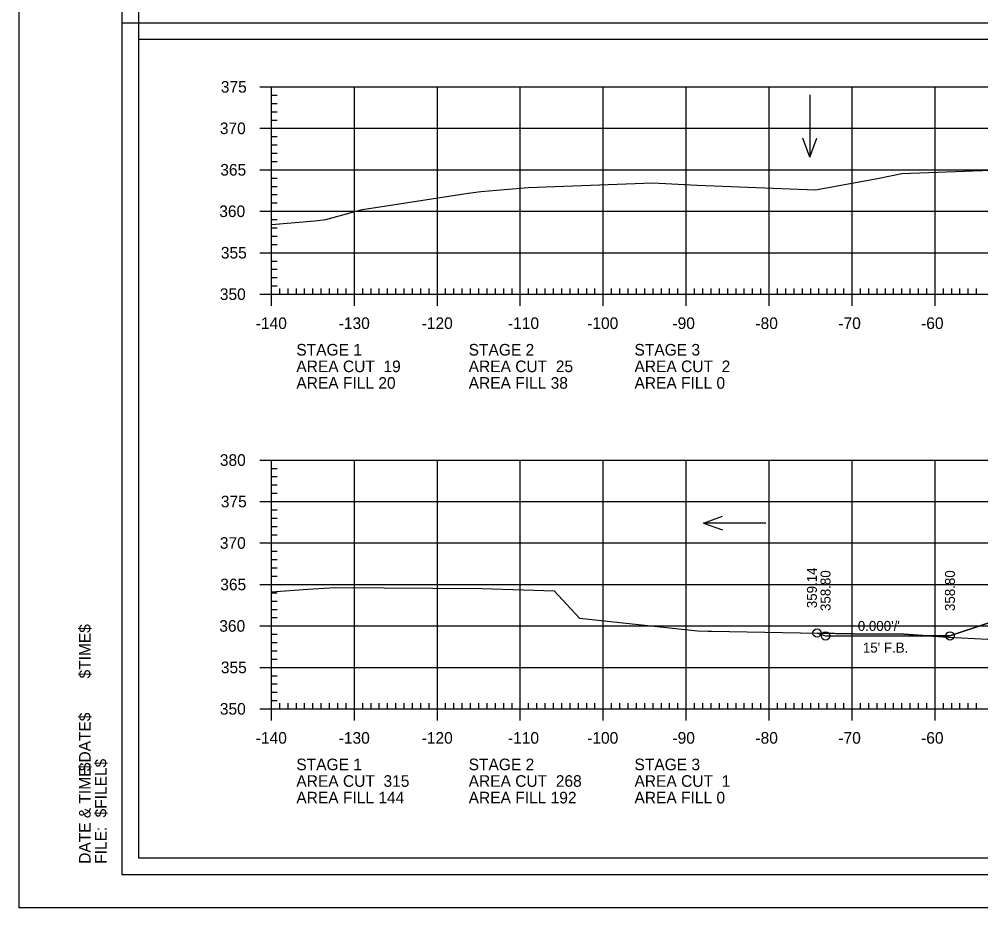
# Model space of a CAD drawing. Extents: x 1368910 to 1369601, y 380116 to 380950.
# Drawn here: x 1368909.8 to 1369025.7, y 380523.8 to 380630.9 of the extents above; entities that cross this region are included whole.
import ezdxf

# ---------------------------------------------------------------- set-up
doc = ezdxf.new("R2010")
doc.units = 0
for name, color, linetype in [('_STAGE 2 CUT', 7, 'Continuous'), ('_STAGE 2 FILL', 7, 'Continuous'), ('R_Axis', 7, 'Continuous'), ('R_Axis Annot', 7, 'Continuous'), ('R_Border', 7, 'Continuous'), ('R_Border Notes', 7, 'Continuous'), ('R_Border Plan-Plan', 7, 'Continuous'), ('R_Exist Surface', 7, 'Continuous'), ('R_Fin Surface', 7, 'Continuous'), ('R_Grid', 7, 'Continuous'), ('R_No Plot', 7, 'Continuous'), ('R_Water Annot', 7, 'Continuous'), ('R_Xsect Elev', 7, 'Continuous'), ('R_Xsect Slope', 7, 'Continuous')]:
    doc.layers.add(name, color=color, linetype=linetype)

msp = doc.modelspace()

# ---------------------------------------------------------------- linework, layer by layer
at = {"layer": '_STAGE 2 CUT'}
for points in [[(1369019.31, 380556.56), (1369016.48, 380556.75), (1369010.41, 380556.82), (1369010.24, 380556.82), (1369006.01, 380556.9)], [(1369006.01, 380556.9), (1369007.03, 380556.56), (1369010.24, 380556.56), (1369019.31, 380556.56)]]:
    msp.add_lwpolyline(points, dxfattribs=at)
at = {"layer": '_STAGE 2 FILL'}
for points in [[(1369019.31, 380556.56), (1369021.84, 380556.39), (1369031.24, 380555.91), (1369035.71, 380555.81), (1369040.24, 380555.68), (1369046.32, 380555.51), (1369049.52, 380557.76), (1369050.24, 380558.27), (1369056.62, 380562.76), (1369060.24, 380565.31), (1369061.88, 380566.47)], [(1369055.52, 380566.34), (1369050.24, 380565.46), (1369047.24, 380564.96), (1369040.63, 380562.76), (1369040.24, 380562.63), (1369025.63, 380557.76), (1369022.03, 380556.56), (1369019.31, 380556.56)]]:
    msp.add_lwpolyline(points, dxfattribs=at)
at = {"layer": 'R_Axis'}
for p, q in [((1368938.84, 380622.76), (1368941.64, 380622.76)), ((1368940.24, 380597.76), (1368940.24, 380622.76)), ((1368940.24, 380621.76), (1368940.94, 380621.76)), ((1368940.24, 380620.76), (1368940.94, 380620.76)), ((1368940.24, 380619.76), (1368940.94, 380619.76)), ((1368940.24, 380618.76), (1368940.94, 380618.76)), ((1368938.84, 380617.76), (1368941.64, 380617.76)), ((1368940.24, 380616.76), (1368940.94, 380616.76)), ((1368940.24, 380615.76), (1368940.94, 380615.76)), ((1368940.24, 380614.76), (1368940.94, 380614.76)), ((1368940.24, 380613.76), (1368940.94, 380613.76)), ((1368938.84, 380612.76), (1368941.64, 380612.76)), ((1368940.24, 380611.76), (1368940.94, 380611.76)), ((1368940.24, 380610.76), (1368940.94, 380610.76)), ((1368940.24, 380609.76), (1368940.94, 380609.76)), ((1368938.84, 380607.76), (1368941.64, 380607.76)), ((1368940.24, 380608.76), (1368940.94, 380608.76)), ((1368940.24, 380606.76), (1368940.94, 380606.76)), ((1368940.24, 380605.76), (1368940.94, 380605.76)), ((1368940.24, 380604.76), (1368940.94, 380604.76)), ((1368940.24, 380603.76), (1368940.94, 380603.76)), ((1368938.84, 380602.76), (1368941.64, 380602.76)), ((1368940.24, 380601.76), (1368940.94, 380601.76)), ((1368940.24, 380600.76), (1368940.94, 380600.76)), ((1368940.24, 380599.76), (1368940.94, 380599.76)), ((1368940.24, 380596.36), (1368940.24, 380599.16)), ((1368940.24, 380598.76), (1368940.94, 380598.76)), ((1368941.24, 380597.76), (1368941.24, 380598.46)), ((1368942.24, 380597.76), (1368942.24, 380598.46)), ((1368943.24, 380597.76), (1368943.24, 380598.46)), ((1368944.24, 380597.76), (1368944.24, 380598.46)), ((1368945.24, 380597.76), (1368945.24, 380598.46)), ((1368946.24, 380597.76), (1368946.24, 380598.46)), ((1368947.24, 380597.76), (1368947.24, 380598.46)), ((1368948.24, 380597.76), (1368948.24, 380598.46)), ((1368949.24, 380597.76), (1368949.24, 380598.46)), ((1368950.24, 380596.36), (1368950.24, 380599.16)), ((1368951.24, 380597.76), (1368951.24, 380598.46)), ((1368952.24, 380597.76), (1368952.24, 380598.46)), ((1368953.24, 380597.76), (1368953.24, 380598.46)), ((1368954.24, 380597.76), (1368954.24, 380598.46)), ((1368955.24, 380597.76), (1368955.24, 380598.46)), ((1368956.24, 380597.76), (1368956.24, 380598.46)), ((1368957.24, 380597.76), (1368957.24, 380598.46)), ((1368958.24, 380597.76), (1368958.24, 380598.46)), ((1368959.24, 380597.76), (1368959.24, 380598.46)), ((1368960.24, 380596.36), (1368960.24, 380599.16)), ((1368961.24, 380597.76), (1368961.24, 380598.46)), ((1368962.24, 380597.76), (1368962.24, 380598.46)), ((1368963.24, 380597.76), (1368963.24, 380598.46)), ((1368964.24, 380597.76), (1368964.24, 380598.46)), ((1368965.24, 380597.76), (1368965.24, 380598.46)), ((1368966.24, 380597.76), (1368966.24, 380598.46)), ((1368967.24, 380597.76), (1368967.24, 380598.46)), ((1368968.24, 380597.76), (1368968.24, 380598.46)), ((1368969.24, 380597.76), (1368969.24, 380598.46)), ((1368970.24, 380596.36), (1368970.24, 380599.16)), ((1368971.24, 380597.76), (1368971.24, 380598.46)), ((1368972.24, 380597.76), (1368972.24, 380598.46)), ((1368973.24, 380597.76), (1368973.24, 380598.46)), ((1368974.24, 380597.76), (1368974.24, 380598.46)), ((1368975.24, 380597.76), (1368975.24, 380598.46)), ((1368976.24, 380597.76), (1368976.24, 380598.46)), ((1368977.24, 380597.76), (1368977.24, 380598.46)), ((1368978.24, 380597.76), (1368978.24, 380598.46)), ((1368979.24, 380597.76), (1368979.24, 380598.46)), ((1368980.24, 380596.36), (1368980.24, 380599.16)), ((1368981.24, 380597.76), (1368981.24, 380598.46)), ((1368982.24, 380597.76), (1368982.24, 380598.46)), ((1368983.24, 380597.76), (1368983.24, 380598.46)), ((1368984.24, 380597.76), (1368984.24, 380598.46)), ((1368985.24, 380597.76), (1368985.24, 380598.46)), ((1368986.24, 380597.76), (1368986.24, 380598.46)), ((1368987.24, 380597.76), (1368987.24, 380598.46)), ((1368988.24, 380597.76), (1368988.24, 380598.46)), ((1368989.24, 380597.76), (1368989.24, 380598.46)), ((1368990.24, 380596.36), (1368990.24, 380599.16)), ((1368991.24, 380597.76), (1368991.24, 380598.46)), ((1368992.24, 380597.76), (1368992.24, 380598.46)), ((1368993.24, 380597.76), (1368993.24, 380598.46)), ((1368994.24, 380597.76), (1368994.24, 380598.46)), ((1368995.24, 380597.76), (1368995.24, 380598.46)), ((1368996.24, 380597.76), (1368996.24, 380598.46)), ((1368997.24, 380597.76), (1368997.24, 380598.46)), ((1368998.24, 380597.76), (1368998.24, 380598.46)), ((1368999.24, 380597.76), (1368999.24, 380598.46)), ((1369000.24, 380596.36), (1369000.24, 380599.16)), ((1369001.24, 380597.76), (1369001.24, 380598.46)), ((1369002.24, 380597.76), (1369002.24, 380598.46)), ((1369003.24, 380597.76), (1369003.24, 380598.46)), ((1369004.24, 380597.76), (1369004.24, 380598.46)), ((1369005.24, 380597.76), (1369005.24, 380598.46)), ((1369006.24, 380597.76), (1369006.24, 380598.46)), ((1369007.24, 380597.76), (1369007.24, 380598.46)), ((1369008.24, 380597.76), (1369008.24, 380598.46)), ((1369009.24, 380597.76), (1369009.24, 380598.46)), ((1369010.24, 380596.36), (1369010.24, 380599.16)), ((1369011.24, 380597.76), (1369011.24, 380598.46)), ((1369012.24, 380597.76), (1369012.24, 380598.46)), ((1369013.24, 380597.76), (1369013.24, 380598.46)), ((1369014.24, 380597.76), (1369014.24, 380598.46)), ((1369015.24, 380597.76), (1369015.24, 380598.46)), ((1369016.24, 380597.76), (1369016.24, 380598.46)), ((1369017.24, 380597.76), (1369017.24, 380598.46)), ((1369018.24, 380597.76), (1369018.24, 380598.46)), ((1369019.24, 380597.76), (1369019.24, 380598.46)), ((1369020.24, 380596.36), (1369020.24, 380599.16)), ((1369021.24, 380597.76), (1369021.24, 380598.46)), ((1369022.24, 380597.76), (1369022.24, 380598.46)), ((1369023.24, 380597.76), (1369023.24, 380598.46)), ((1369024.24, 380597.76), (1369024.24, 380598.46)), ((1369025.24, 380597.76), (1369025.24, 380598.46)), ((1368938.84, 380597.76), (1368941.64, 380597.76)), ((1368940.24, 380597.76), (1369220.24, 380597.76)), ((1368938.84, 380577.76), (1368941.64, 380577.76)), ((1368940.24, 380547.76), (1368940.24, 380577.76)), ((1368940.24, 380576.76), (1368940.94, 380576.76)), ((1368940.24, 380575.76), (1368940.94, 380575.76)), ((1368940.24, 380574.76), (1368940.94, 380574.76)), ((1368940.24, 380573.76), (1368940.94, 380573.76)), ((1368938.84, 380572.76), (1368941.64, 380572.76)), ((1368940.24, 380571.76), (1368940.94, 380571.76)), ((1368940.24, 380570.76), (1368940.94, 380570.76)), ((1368940.24, 380569.76), (1368940.94, 380569.76)), ((1368940.24, 380568.76), (1368940.94, 380568.76)), ((1368938.84, 380567.76), (1368941.64, 380567.76)), ((1368940.24, 380566.76), (1368940.94, 380566.76)), ((1368940.24, 380565.76), (1368940.94, 380565.76)), ((1368940.24, 380564.76), (1368940.94, 380564.76)), ((1368940.24, 380563.76), (1368940.94, 380563.76)), ((1368938.84, 380562.76), (1368941.64, 380562.76)), ((1368940.24, 380561.76), (1368940.94, 380561.76)), ((1368940.24, 380560.76), (1368940.94, 380560.76)), ((1368940.24, 380559.76), (1368940.94, 380559.76)), ((1368940.24, 380558.76), (1368940.94, 380558.76)), ((1368938.84, 380557.76), (1368941.64, 380557.76)), ((1368940.24, 380556.76), (1368940.94, 380556.76)), ((1368940.24, 380555.76), (1368940.94, 380555.76)), ((1368940.24, 380554.76), (1368940.94, 380554.76)), ((1368940.24, 380553.76), (1368940.94, 380553.76)), ((1368938.84, 380552.76), (1368941.64, 380552.76)), ((1368940.24, 380551.76), (1368940.94, 380551.76)), ((1368940.24, 380550.76), (1368940.94, 380550.76)), ((1368940.24, 380549.76), (1368940.94, 380549.76)), ((1368940.24, 380546.36), (1368940.24, 380549.16)), ((1368940.24, 380548.76), (1368940.94, 380548.76)), ((1368950.24, 380546.36), (1368950.24, 380549.16)), ((1368960.24, 380546.36), (1368960.24, 380549.16)), ((1368970.24, 380546.36), (1368970.24, 380549.16)), ((1368980.24, 380546.36), (1368980.24, 380549.16)), ((1368990.24, 380546.36), (1368990.24, 380549.16)), ((1369000.24, 380546.36), (1369000.24, 380549.16)), ((1369010.24, 380546.36), (1369010.24, 380549.16)), ((1369020.24, 380546.36), (1369020.24, 380549.16)), ((1368938.84, 380547.76), (1368941.64, 380547.76)), ((1368940.24, 380547.76), (1369220.24, 380547.76)), ((1368941.24, 380547.76), (1368941.24, 380548.46)), ((1368942.24, 380547.76), (1368942.24, 380548.46)), ((1368943.24, 380547.76), (1368943.24, 380548.46)), ((1368944.24, 380547.76), (1368944.24, 380548.46)), ((1368945.24, 380547.76), (1368945.24, 380548.46)), ((1368946.24, 380547.76), (1368946.24, 380548.46)), ((1368947.24, 380547.76), (1368947.24, 380548.46)), ((1368948.24, 380547.76), (1368948.24, 380548.46)), ((1368949.24, 380547.76), (1368949.24, 380548.46)), ((1368951.24, 380547.76), (1368951.24, 380548.46)), ((1368952.24, 380547.76), (1368952.24, 380548.46)), ((1368953.24, 380547.76), (1368953.24, 380548.46)), ((1368954.24, 380547.76), (1368954.24, 380548.46)), ((1368955.24, 380547.76), (1368955.24, 380548.46)), ((1368956.24, 380547.76), (1368956.24, 380548.46)), ((1368957.24, 380547.76), (1368957.24, 380548.46)), ((1368958.24, 380547.76), (1368958.24, 380548.46)), ((1368959.24, 380547.76), (1368959.24, 380548.46)), ((1368961.24, 380547.76), (1368961.24, 380548.46)), ((1368962.24, 380547.76), (1368962.24, 380548.46)), ((1368963.24, 380547.76), (1368963.24, 380548.46)), ((1368964.24, 380547.76), (1368964.24, 380548.46)), ((1368965.24, 380547.76), (1368965.24, 380548.46)), ((1368966.24, 380547.76), (1368966.24, 380548.46)), ((1368967.24, 380547.76), (1368967.24, 380548.46)), ((1368968.24, 380547.76), (1368968.24, 380548.46)), ((1368969.24, 380547.76), (1368969.24, 380548.46)), ((1368971.24, 380547.76), (1368971.24, 380548.46)), ((1368972.24, 380547.76), (1368972.24, 380548.46)), ((1368973.24, 380547.76), (1368973.24, 380548.46)), ((1368974.24, 380547.76), (1368974.24, 380548.46)), ((1368975.24, 380547.76), (1368975.24, 380548.46)), ((1368976.24, 380547.76), (1368976.24, 380548.46)), ((1368977.24, 380547.76), (1368977.24, 380548.46)), ((1368978.24, 380547.76), (1368978.24, 380548.46)), ((1368979.24, 380547.76), (1368979.24, 380548.46)), ((1368981.24, 380547.76), (1368981.24, 380548.46)), ((1368982.24, 380547.76), (1368982.24, 380548.46)), ((1368983.24, 380547.76), (1368983.24, 380548.46)), ((1368984.24, 380547.76), (1368984.24, 380548.46)), ((1368985.24, 380547.76), (1368985.24, 380548.46)), ((1368986.24, 380547.76), (1368986.24, 380548.46)), ((1368987.24, 380547.76), (1368987.24, 380548.46)), ((1368988.24, 380547.76), (1368988.24, 380548.46)), ((1368989.24, 380547.76), (1368989.24, 380548.46)), ((1368991.24, 380547.76), (1368991.24, 380548.46)), ((1368992.24, 380547.76), (1368992.24, 380548.46)), ((1368993.24, 380547.76), (1368993.24, 380548.46)), ((1368994.24, 380547.76), (1368994.24, 380548.46)), ((1368995.24, 380547.76), (1368995.24, 380548.46)), ((1368996.24, 380547.76), (1368996.24, 380548.46)), ((1368997.24, 380547.76), (1368997.24, 380548.46)), ((1368998.24, 380547.76), (1368998.24, 380548.46)), ((1368999.24, 380547.76), (1368999.24, 380548.46)), ((1369001.24, 380547.76), (1369001.24, 380548.46)), ((1369002.24, 380547.76), (1369002.24, 380548.46)), ((1369003.24, 380547.76), (1369003.24, 380548.46)), ((1369004.24, 380547.76), (1369004.24, 380548.46)), ((1369005.24, 380547.76), (1369005.24, 380548.46)), ((1369006.24, 380547.76), (1369006.24, 380548.46)), ((1369007.24, 380547.76), (1369007.24, 380548.46)), ((1369008.24, 380547.76), (1369008.24, 380548.46)), ((1369009.24, 380547.76), (1369009.24, 380548.46)), ((1369011.24, 380547.76), (1369011.24, 380548.46)), ((1369012.24, 380547.76), (1369012.24, 380548.46)), ((1369013.24, 380547.76), (1369013.24, 380548.46)), ((1369014.24, 380547.76), (1369014.24, 380548.46)), ((1369015.24, 380547.76), (1369015.24, 380548.46)), ((1369016.24, 380547.76), (1369016.24, 380548.46)), ((1369017.24, 380547.76), (1369017.24, 380548.46)), ((1369018.24, 380547.76), (1369018.24, 380548.46)), ((1369019.24, 380547.76), (1369019.24, 380548.46)), ((1369021.24, 380547.76), (1369021.24, 380548.46)), ((1369022.24, 380547.76), (1369022.24, 380548.46)), ((1369023.24, 380547.76), (1369023.24, 380548.46)), ((1369024.24, 380547.76), (1369024.24, 380548.46)), ((1369025.24, 380547.76), (1369025.24, 380548.46))]:
    msp.add_line(p, q, dxfattribs=at)
at = {"layer": 'R_Border'}
for p, q in [((1368922.24, 380527.76), (1368922.24, 380733.22)), ((1368922.24, 380527.76), (1368922.24, 380527.76)), ((1369238.42, 380527.76), (1368922.24, 380527.76))]:
    msp.add_line(p, q, dxfattribs=at)
at = {"layer": 'R_Border Plan-Plan'}
msp.add_line((1368922.24, 380630.49), (1369238.42, 380630.49), dxfattribs=at)
at = {"layer": 'R_Exist Surface'}
for points in [[(1368940.24, 380606.18), (1368945.48, 380606.6), (1368946.8, 380606.78), (1368950.45, 380607.79), (1368951.2, 380607.96), (1368963.97, 380609.96), (1368965.48, 380610.16), (1368971.2, 380610.62), (1368986.2, 380611.2), (1368991.54, 380610.91), (1369005.84, 380610.36), (1369013.5, 380611.73), (1369016.21, 380612.32), (1369033.48, 380612.94)], [(1368940.24, 380561.86), (1368944.63, 380562.18), (1368947.91, 380562.39), (1368965.61, 380562.26), (1368970.64, 380562.13), (1368974.3, 380561.99), (1368977.39, 380558.68), (1368991.61, 380557.16), (1368992.85, 380557.13), (1368993.32, 380557.12), (1369010.41, 380556.82), (1369016.48, 380556.75), (1369021.84, 380556.39), (1369031.24, 380555.91)]]:
    msp.add_lwpolyline(points, dxfattribs=at)
at = {"layer": 'R_Fin Surface'}
msp.add_lwpolyline([(1369006.01, 380556.9), (1369007.03, 380556.56), (1369022.03, 380556.56), (1369047.24, 380564.96), (1369055.52, 380566.34), (1369061.24, 380567.3), (1369069.24, 380567.62), (1369080.24, 380567.84), (1369091.24, 380567.62), (1369099.24, 380567.3), (1369105.15, 380566.34), (1369113.24, 380565.03), (1369138.05, 380556.76), (1369153.05, 380556.76), (1369156.96, 380558.06)], dxfattribs=at)
at = {"layer": 'R_Grid'}
for p, q in [((1368940.24, 380622.76), (1369220.24, 380622.76)), ((1368940.24, 380597.76), (1368940.24, 380622.76)), ((1368950.24, 380597.76), (1368950.24, 380622.76)), ((1368960.24, 380597.76), (1368960.24, 380622.76)), ((1368970.24, 380597.76), (1368970.24, 380622.76)), ((1368980.24, 380597.76), (1368980.24, 380622.76)), ((1368990.24, 380597.76), (1368990.24, 380622.76)), ((1369000.24, 380597.76), (1369000.24, 380622.76)), ((1369010.24, 380597.76), (1369010.24, 380622.76)), ((1369020.24, 380597.76), (1369020.24, 380622.76)), ((1368940.24, 380617.76), (1369220.24, 380617.76)), ((1368940.24, 380612.76), (1369220.24, 380612.76)), ((1368940.24, 380607.76), (1369220.24, 380607.76)), ((1368940.24, 380602.76), (1369220.24, 380602.76)), ((1368940.24, 380597.76), (1369220.24, 380597.76)), ((1368940.24, 380577.76), (1369220.24, 380577.76)), ((1368940.24, 380547.76), (1368940.24, 380577.76)), ((1368950.24, 380547.76), (1368950.24, 380577.76)), ((1368960.24, 380547.76), (1368960.24, 380577.76)), ((1368970.24, 380547.76), (1368970.24, 380577.76)), ((1368980.24, 380547.76), (1368980.24, 380577.76)), ((1368990.24, 380547.76), (1368990.24, 380577.76)), ((1369000.24, 380547.76), (1369000.24, 380577.76)), ((1369010.24, 380547.76), (1369010.24, 380577.76)), ((1369020.24, 380547.76), (1369020.24, 380577.76)), ((1368940.24, 380572.76), (1369220.24, 380572.76)), ((1368940.24, 380567.76), (1369220.24, 380567.76)), ((1368940.24, 380562.76), (1369220.24, 380562.76)), ((1368940.24, 380557.76), (1369220.24, 380557.76)), ((1368940.24, 380552.76), (1369220.24, 380552.76)), ((1368940.24, 380547.76), (1369220.24, 380547.76))]:
    msp.add_line(p, q, dxfattribs=at)
at = {"layer": 'R_No Plot'}
for points in [[(1368909.84, 380737.11), (1369243.18, 380737.11), (1369243.18, 380523.78), (1368909.84, 380523.78)], [(1368924.24, 380731.22), (1369173.78, 380731.22), (1369173.78, 380721.34), (1369191.32, 380721.34), (1369215.42, 380721.34), (1369215.42, 380699.01), (1369236.42, 380699.01), (1369236.42, 380529.76), (1368924.24, 380529.76)], [(1368924.24, 380628.49), (1369236.42, 380628.49), (1369236.42, 380529.76), (1368924.24, 380529.76)]]:
    msp.add_lwpolyline(points, close=True, dxfattribs=at)
for centre in [(1369006.01, 380556.9), (1369007.03, 380556.56), (1369022.03, 380556.56)]:
    msp.add_circle(centre, 0.5, dxfattribs=at)
at = {"layer": 'R_Water Annot'}
for p, q in [((1369005.15, 380621.81), (1369005.15, 380614.27)), ((1369005.15, 380614.27), (1369004.31, 380616.58)), ((1369005.15, 380614.27), (1369005.99, 380616.58)), ((1368992.31, 380570.17), (1368994.61, 380571.01)), ((1368999.85, 380570.17), (1368992.31, 380570.17)), ((1368992.31, 380570.17), (1368994.61, 380569.33))]:
    msp.add_line(p, q, dxfattribs=at)

# ---------------------------------------------------------------- texts
at = {"layer": 'R_Axis Annot'}
for s, p in [('375', (1368934.14, 380622.06)), ('370', (1368934.02, 380617.06)), ('365', (1368934.07, 380612.06)), ('360', (1368933.95, 380607.06)), ('355', (1368934.14, 380602.06)), ('350', (1368934.02, 380597.06)), ('-140', (1368938.35, 380593.56)), ('-130', (1368948.35, 380593.56)), ('-120', (1368958.35, 380593.56)), ('-110', (1368968.75, 380593.56)), ('-100', (1368978.3, 380593.56)), ('-90', (1368988.58, 380593.56)), ('-80', (1368998.58, 380593.56)), ('-70', (1369008.58, 380593.56)), ('-60', (1369018.55, 380593.56)), ('STAGE 1', (1368943.24, 380590.36)), ('STAGE 2', (1368964.01, 380590.36)), ('STAGE 3', (1368984, 380590.36)), ('AREA CUT  19', (1368943.24, 380588.36)), ('AREA CUT  25', (1368964.01, 380588.36)), ('AREA CUT  2', (1368984, 380588.36)), ('AREA FILL 20', (1368943.24, 380586.36)), ('AREA FILL 38', (1368964.01, 380586.36)), ('AREA FILL 0', (1368984, 380586.36)), ('380', (1368934.02, 380577.06)), ('375', (1368934.14, 380572.06)), ('370', (1368934.02, 380567.06)), ('365', (1368934.07, 380562.06)), ('360', (1368933.95, 380557.06)), ('355', (1368934.14, 380552.06)), ('350', (1368934.02, 380547.06)), ('-140', (1368938.35, 380543.56)), ('-130', (1368948.35, 380543.56)), ('-120', (1368958.35, 380543.56)), ('-110', (1368968.75, 380543.56)), ('-100', (1368978.3, 380543.56)), ('-90', (1368988.58, 380543.56)), ('-80', (1368998.58, 380543.56)), ('-70', (1369008.58, 380543.56)), ('-60', (1369018.55, 380543.56)), ('STAGE 1', (1368943.24, 380540.36)), ('STAGE 2', (1368964.01, 380540.36)), ('STAGE 3', (1368984, 380540.36)), ('AREA CUT  315', (1368943.24, 380538.36)), ('AREA CUT  268', (1368964.01, 380538.36)), ('AREA CUT  1', (1368984, 380538.36)), ('AREA FILL 144', (1368943.24, 380536.36)), ('AREA FILL 192', (1368964.01, 380536.36)), ('AREA FILL 0', (1368984, 380536.36))]:
    msp.add_text(s, height=1.4, dxfattribs=at).set_placement(p)
at = {"layer": 'R_Border Notes'}
for s, height, p in [('$TIME$', 1.397, (1368918.44, 380551.43)), ('$DATE$', 1.397, (1368918.44, 380540.25)), ('$FILEL$', 1.397, (1368920.36, 380534.67)), ('DATE & TIME:', 1.3968, (1368918.44, 380529.08)), ('FILE: ', 1.397, (1368920.36, 380529.08))]:
    msp.add_text(s, height=height, rotation=90, dxfattribs=at).set_placement(p)
at = {"layer": 'R_Xsect Elev'}
for s, p in [('359.14', (1369005.99, 380559.9)), ('358.80', (1369007.63, 380559.56)), ('358.80', (1369022.63, 380559.56))]:
    msp.add_text(s, height=1.2, rotation=90, dxfattribs=at).set_placement(p)
at = {"layer": 'R_Xsect Slope'}
for s, p in [("0.000'/'", (1369010.92, 380557.16)), ("15' F.B.", (1369011.53, 380554.54))]:
    msp.add_text(s, height=1.2, rotation=360, dxfattribs=at).set_placement(p)

doc.saveas('drawing.dxf')
